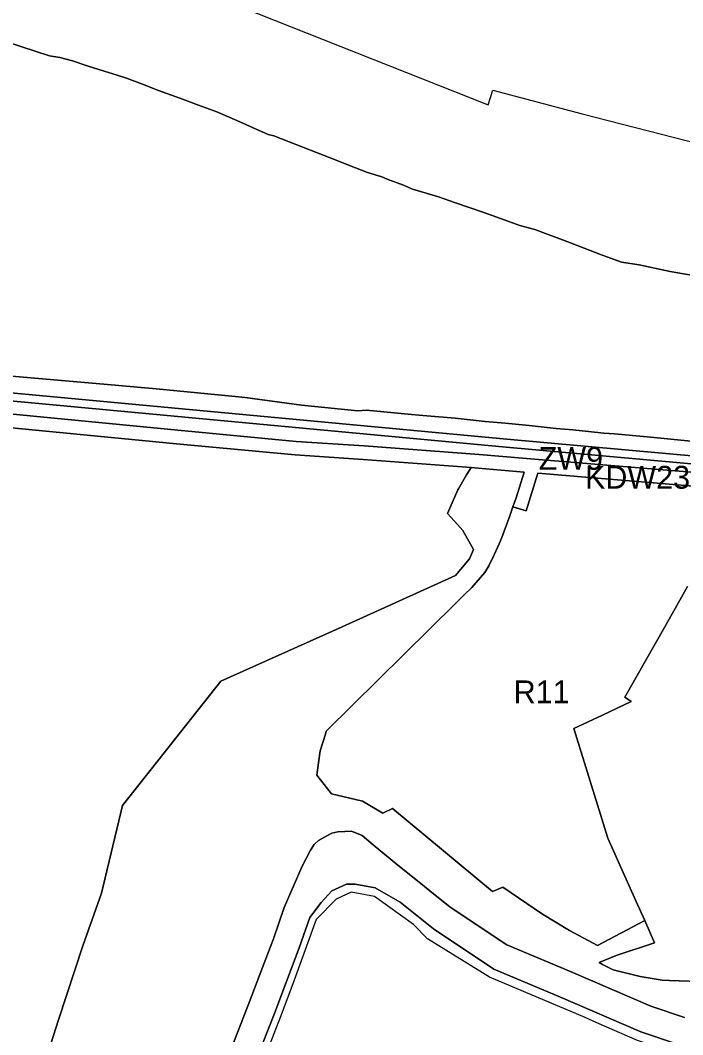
# Model space of a CAD drawing. Extents: x 7428841 to 7433518, y 5545054 to 5546840.
# Drawn here: x 7432279.9 to 7432570.4, y 5546084.6 to 5546529.2 of the extents above; entities that cross this region are included whole.
import ezdxf

# ---------------------------------------------------------------- set-up
doc = ezdxf.new("R2010")
doc.units = 0
for name, color, linetype in [('linie_rozgraniczajace', 7, 'Continuous'), ('linie_zabudowy_nieprzekraczalne', 7, 'Continuous'), ('oznaczenia_przeznaczen', 7, 'Continuous')]:
    doc.layers.add(name, color=color, linetype=linetype)

msp = doc.modelspace()

# ---------------------------------------------------------------- linework, layer by layer
at = {"layer": 'linie_rozgraniczajace'}
for points in [[(7431963.05, 5546587.15), (7431963.34, 5546642.13), (7432009.15, 5546643.61), (7432065.32, 5546635.38), (7432116.01, 5546624.29), (7432130.65, 5546621.08), (7432260.46, 5546578.5), (7432333.87, 5546557.74), (7432337.43, 5546555.86), (7432376.88, 5546534.94), (7432485.15, 5546492.1), (7432487.19, 5546498.64), (7432526.29, 5546488.21), (7432601.02, 5546469.08), (7432678.54, 5546456.61), (7432751.33, 5546453.06), (7432763.46, 5546452.71), (7432820.67, 5546451.02), (7432919.88, 5546450.2)], [(7432268.29, 5546521.66), (7432280.51, 5546517.65), (7432292.74, 5546513.65), (7432297.19, 5546512.92), (7432302.72, 5546511.41), (7432309.7, 5546509.14), (7432316.67, 5546506.87), (7432322.41, 5546505.16), (7432326.51, 5546503.85), (7432333.53, 5546501.15), (7432340.54, 5546498.45), (7432349.85, 5546495.04), (7432357.98, 5546492.06), (7432366.12, 5546489.08), (7432374.84, 5546485.22), (7432388.56, 5546479.14), (7432391.05, 5546478.57), (7432397.81, 5546475.97), (7432415.75, 5546468.97), (7432426.93, 5546464.56), (7432432.15, 5546462.51), (7432438.38, 5546460.65), (7432440.79, 5546459.59), (7432447.9, 5546456.91), (7432451.91, 5546455.14), (7432457.89, 5546453.42), (7432463.25, 5546451.88), (7432470.74, 5546449.15), (7432483.13, 5546444.96), (7432494.21, 5546440.96), (7432498.93, 5546439.26), (7432505.57, 5546437.48), (7432519.99, 5546432.04), (7432534.42, 5546426.59), (7432543.52, 5546423.16), (7432551.29, 5546422.08), (7432564.9, 5546419.12), (7432575.01, 5546417.39)], [(7432575.01, 5546417.39), (7432564.9, 5546419.12), (7432551.29, 5546422.08), (7432543.52, 5546423.16), (7432534.42, 5546426.59), (7432519.99, 5546432.04), (7432505.57, 5546437.48), (7432498.93, 5546439.26), (7432494.21, 5546440.96), (7432483.13, 5546444.96), (7432470.74, 5546449.15), (7432463.25, 5546451.88), (7432457.89, 5546453.42), (7432451.91, 5546455.14), (7432447.9, 5546456.91), (7432440.79, 5546459.59), (7432438.38, 5546460.65), (7432432.15, 5546462.51), (7432426.93, 5546464.56), (7432415.75, 5546468.97), (7432397.81, 5546475.97), (7432391.05, 5546478.57), (7432388.56, 5546479.14), (7432374.84, 5546485.22), (7432366.12, 5546489.08), (7432357.98, 5546492.06), (7432349.85, 5546495.04), (7432340.54, 5546498.45), (7432333.53, 5546501.15), (7432326.51, 5546503.85), (7432322.41, 5546505.16), (7432316.67, 5546506.87), (7432309.7, 5546509.14), (7432302.72, 5546511.41), (7432297.19, 5546512.92), (7432292.74, 5546513.65), (7432280.51, 5546517.65), (7432268.29, 5546521.66)], [(7432877.8, 5546310.25), (7432808.08, 5546316.9), (7432738.37, 5546323.55), (7432614.98, 5546334.67), (7432491.6, 5546345.79), (7432259.96, 5546367.34), (7432028.32, 5546388.89), (7431987.12, 5546392.49), (7431987.22, 5546393.91), (7431979.01, 5546401.39)], [(7432877.5, 5546306.77), (7432807.79, 5546313.42), (7432738.07, 5546320.06), (7432614.7, 5546331.18), (7432491.32, 5546342.3), (7432259.69, 5546363.86), (7432028.07, 5546385.41), (7431995.46, 5546388.26), (7431986.88, 5546389.01), (7431987.12, 5546392.49), (7432028.32, 5546388.89), (7432259.96, 5546367.34), (7432491.6, 5546345.79), (7432614.98, 5546334.67), (7432738.37, 5546323.55), (7432808.08, 5546316.9), (7432877.8, 5546310.25)], [(7432620.05, 5546340.29), (7432554.76, 5546346.62), (7432540.45, 5546348.01), (7432535.87, 5546348.32), (7432529.03, 5546349.03), (7432522.19, 5546349.74), (7432514.92, 5546350.27), (7432503.04, 5546351.65), (7432492.58, 5546352.61), (7432483.72, 5546353.3), (7432477.15, 5546354.05), (7432470.58, 5546354.81), (7432458.18, 5546355.8), (7432451.49, 5546356.45), (7432431.73, 5546358.4), (7432427.87, 5546358.07), (7432403.2, 5546360.58), (7432378.5, 5546363.92), (7432372.61, 5546364.48), (7432353.12, 5546366.36), (7432339.53, 5546367.67), (7432316.46, 5546369.67), (7432267.52, 5546373.91)], [(7432267.52, 5546373.91), (7432316.46, 5546369.67), (7432339.53, 5546367.67), (7432353.12, 5546366.36), (7432372.61, 5546364.48), (7432378.5, 5546363.92), (7432403.2, 5546360.58), (7432427.87, 5546358.07), (7432431.73, 5546358.4), (7432451.49, 5546356.45), (7432458.18, 5546355.8), (7432470.58, 5546354.81), (7432477.15, 5546354.05), (7432483.72, 5546353.3), (7432492.58, 5546352.61), (7432503.04, 5546351.65), (7432514.92, 5546350.27), (7432522.19, 5546349.74), (7432529.03, 5546349.03), (7432535.87, 5546348.32), (7432540.45, 5546348.01), (7432554.76, 5546346.62), (7432620.05, 5546340.29)], [(7432259.69, 5546363.86), (7432491.32, 5546342.3), (7432614.7, 5546331.18), (7432738.07, 5546320.06), (7432807.79, 5546313.42), (7432877.5, 5546306.77)], [(7432859.86, 5546304.41), (7432799.1, 5546309.67), (7432742.58, 5546314.69), (7432713.24, 5546317.65), (7432694.84, 5546319.51), (7432669.38, 5546322.17), (7432609.55, 5546328.28), (7432501.83, 5546337.14), (7432481.2, 5546338.91), (7432430.74, 5546342.72), (7432400.88, 5546344.67), (7432349.02, 5546349.5), (7432259.88, 5546358.16)], [(7432259.88, 5546358.16), (7432349.02, 5546349.5), (7432400.88, 5546344.67), (7432430.74, 5546342.72), (7432481.2, 5546338.91), (7432501.83, 5546337.14), (7432609.55, 5546328.28), (7432669.38, 5546322.17), (7432694.84, 5546319.51), (7432713.24, 5546317.65), (7432742.58, 5546314.69), (7432799.1, 5546309.67), (7432859.86, 5546304.41)], [(7432259.35, 5546352.19), (7432348.45, 5546343.52), (7432400.4, 5546338.69), (7432430.32, 5546336.73), (7432477.56, 5546333.17), (7432475.55, 5546329.92), (7432472.02, 5546323.82), (7432471.73, 5546323.37), (7432467.3, 5546313.08), (7432471.58, 5546308.27), (7432474.02, 5546305.54), (7432478.6, 5546297.33), (7432476.87, 5546293.21), (7432470.77, 5546285.83), (7432421.07, 5546263.37), (7432367.83, 5546239.52), (7432324.74, 5546185.03), (7432315.57, 5546146.64), (7432307.33, 5546123.56), (7432296.62, 5546091.15), (7432288.79, 5546066.47)], [(7432859.33, 5546298.44), (7432798.57, 5546303.7), (7432742.01, 5546308.72), (7432712.64, 5546311.68), (7432694.22, 5546313.54), (7432668.76, 5546316.2), (7432604.63, 5546322.59), (7432506.91, 5546330.7), (7432501.69, 5546314.18), (7432495.98, 5546316), (7432497.42, 5546319.96), (7432500.86, 5546331.2), (7432480.72, 5546332.93), (7432477.56, 5546333.17), (7432430.32, 5546336.73), (7432400.4, 5546338.69), (7432348.45, 5546343.52), (7432259.35, 5546352.19)], [(7432288.79, 5546066.47), (7432296.62, 5546091.15), (7432307.33, 5546123.56), (7432315.57, 5546146.64), (7432324.74, 5546185.03), (7432367.83, 5546239.52), (7432421.07, 5546263.37), (7432470.77, 5546285.83), (7432476.87, 5546293.21), (7432478.6, 5546297.33), (7432474.02, 5546305.54), (7432471.58, 5546308.27), (7432467.3, 5546313.08), (7432471.73, 5546323.37), (7432472.02, 5546323.82), (7432475.55, 5546329.92), (7432477.56, 5546333.17), (7432480.72, 5546332.93), (7432500.86, 5546331.2), (7432497.42, 5546319.96), (7432495.98, 5546316), (7432495.97, 5546315.97), (7432494.54, 5546312.04), (7432491.01, 5546302.52), (7432489.96, 5546299.8), (7432487.68, 5546294.97), (7432485.4, 5546290.14), (7432483.6, 5546287.18), (7432477.97, 5546280.6), (7432474.47, 5546277.2), (7432470.97, 5546273.8), (7432413.97, 5546217.64), (7432413.76, 5546216.32), (7432411.45, 5546209.07), (7432410.73, 5546203.74), (7432410.01, 5546198.4), (7432413.17, 5546194.29), (7432416.32, 5546190.18), (7432429.99, 5546186.9), (7432438.88, 5546181.73), (7432443.11, 5546183.74), (7432486.99, 5546147.41), (7432491.48, 5546149.29), (7432508.93, 5546137.39), (7432520.8, 5546130.22), (7432533.07, 5546123.68), (7432553.75, 5546134.59), (7432558.09, 5546124.91), (7432541.26, 5546119.36), (7432533.82, 5546116.23), (7432535.19, 5546115.43), (7432539.95, 5546113.07), (7432551.76, 5546110.06), (7432561.43, 5546108.57), (7432564.66, 5546108.37), (7432590.35, 5546107.46)], [(7432572.49, 5546281.01), (7432563.21, 5546264.43), (7432545.01, 5546232.51), (7432547.87, 5546230.6), (7432535.17, 5546224.65), (7432522.59, 5546218.74), (7432537.58, 5546170.68), (7432549.84, 5546143.3), (7432553.75, 5546134.59), (7432533.07, 5546123.68), (7432520.8, 5546130.22), (7432508.93, 5546137.39), (7432491.48, 5546149.29), (7432486.99, 5546147.41), (7432443.11, 5546183.74), (7432438.88, 5546181.73), (7432429.99, 5546186.9), (7432416.32, 5546190.18), (7432413.17, 5546194.29), (7432410.01, 5546198.4), (7432410.73, 5546203.74), (7432411.45, 5546209.07), (7432413.76, 5546216.32), (7432413.97, 5546217.64), (7432470.97, 5546273.8), (7432474.47, 5546277.2), (7432477.97, 5546280.6), (7432483.6, 5546287.18), (7432485.4, 5546290.14), (7432487.68, 5546294.97), (7432489.96, 5546299.8), (7432491.01, 5546302.52), (7432494.54, 5546312.04), (7432495.97, 5546315.97), (7432495.98, 5546316), (7432501.69, 5546314.18), (7432506.91, 5546330.7), (7432604.63, 5546322.59)], [(7432590.35, 5546107.46), (7432564.66, 5546108.37), (7432561.43, 5546108.57), (7432551.76, 5546110.06), (7432539.95, 5546113.07), (7432535.19, 5546115.43), (7432533.82, 5546116.23), (7432541.26, 5546119.36), (7432558.09, 5546124.91), (7432553.75, 5546134.59), (7432549.84, 5546143.3), (7432537.58, 5546170.68), (7432522.59, 5546218.74), (7432535.17, 5546224.65), (7432547.87, 5546230.6), (7432545.01, 5546232.51), (7432563.21, 5546264.43), (7432572.49, 5546281.01)], [(7432370.28, 5546073.1), (7432379.89, 5546097.52), (7432385.41, 5546112.1), (7432390.93, 5546126.68), (7432395.62, 5546140.36), (7432403.56, 5546158.52), (7432407.13, 5546165.56), (7432408.83, 5546168.02), (7432410.69, 5546169.74), (7432414.63, 5546171.9), (7432416.53, 5546172.88), (7432419.14, 5546173.52), (7432422.16, 5546173.67), (7432425.19, 5546173.82), (7432429.86, 5546171.95), (7432434.67, 5546167.84), (7432445.47, 5546158.88), (7432454.06, 5546152.02), (7432462.64, 5546145.15), (7432468.23, 5546140.63), (7432480.73, 5546132.31), (7432493.23, 5546124), (7432521.46, 5546112.16), (7432556.36, 5546097.09), (7432571.13, 5546092.14)], [(7432429.86, 5546171.95), (7432425.19, 5546173.82), (7432422.16, 5546173.67), (7432419.14, 5546173.52), (7432416.53, 5546172.88), (7432414.63, 5546171.9), (7432410.69, 5546169.74), (7432408.83, 5546168.02), (7432407.13, 5546165.56), (7432403.56, 5546158.52), (7432395.62, 5546140.36), (7432390.93, 5546126.68), (7432385.41, 5546112.1), (7432379.89, 5546097.52), (7432370.28, 5546073.1)], [(7432571.13, 5546092.14), (7432556.36, 5546097.09), (7432521.46, 5546112.16), (7432493.23, 5546124), (7432480.73, 5546132.31), (7432468.23, 5546140.63), (7432462.64, 5546145.15), (7432454.06, 5546152.02), (7432445.47, 5546158.88), (7432434.67, 5546167.84), (7432429.86, 5546171.95)], [(7432568.2, 5546080.47), (7432552.06, 5546085.88), (7432516.82, 5546101.1), (7432487.54, 5546113.37), (7432461.12, 5546130.95), (7432446.49, 5546142.71), (7432435.6, 5546149.02), (7432426.76, 5546150.59), (7432422.94, 5546150.56), (7432416.59, 5546147.7), (7432411.88, 5546142.59), (7432406.81, 5546136), (7432402.26, 5546122.75), (7432391.09, 5546093.19), (7432381.44, 5546068.71)], [(7432381.44, 5546068.71), (7432391.09, 5546093.19), (7432402.26, 5546122.75), (7432406.81, 5546136), (7432411.88, 5546142.59), (7432416.59, 5546147.7), (7432422.94, 5546150.56), (7432426.76, 5546150.59), (7432435.6, 5546149.02), (7432446.49, 5546142.71), (7432461.12, 5546130.95), (7432487.54, 5546113.37), (7432516.82, 5546101.1), (7432552.06, 5546085.88), (7432568.2, 5546080.47)]]:
    msp.add_lwpolyline(points, dxfattribs=at)
at = {"layer": 'linie_zabudowy_nieprzekraczalne'}
msp.add_lwpolyline([(7432593.63, 5546074.54), (7432591.98, 5546073.8), (7432578.61, 5546074.63), (7432567.22, 5546076.58), (7432550.63, 5546082.14), (7432532.81, 5546089.84), (7432527.7, 5546092.2), (7432485.7, 5546109.81), (7432458.51, 5546126.69), (7432452.41, 5546132.85), (7432435.28, 5546145.13), (7432424.99, 5546147.09), (7432418.39, 5546143.95), (7432409.65, 5546135.03), (7432399.48, 5546106.93), (7432393.88, 5546092.12), (7432381.68, 5546060.94), (7432377.92, 5546051.34), (7432372.72, 5546035.31)], dxfattribs=at)

# ---------------------------------------------------------------- texts
at = {"layer": 'oznaczenia_przeznaczen'}
for s, p in [('ZW9', (7432507.24, 5546332.19)), ('KDW23', (7432527.56, 5546323.93)), ('R11', (7432496.27, 5546229.87))]:
    msp.add_text(s, height=10, dxfattribs=at).set_placement(p)

doc.saveas('drawing.dxf')
